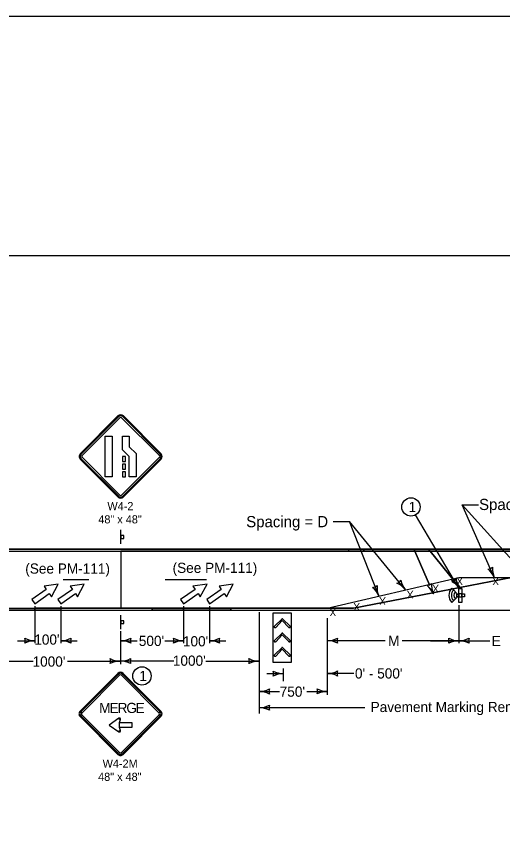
# Model space of a CAD drawing. Extents: x -2135039 to 114557, y -2139150 to -409929.
# Drawn here: x -2130293 to -2129338, y -2138203 to -2136566 of the extents above; entities that cross this region are included whole.
import ezdxf

# ---------------------------------------------------------------- set-up
doc = ezdxf.new("R2010")
doc.units = 0
for name, color, linetype in [('dsnDOTLogo', 7, 'Continuous'), ('dsnStdLabel', 7, 'Continuous'), ('dsnStdLineWork', 7, 'Continuous'), ('dsnStdNote', 7, 'Continuous'), ('dsnStdShading', 7, 'Continuous'), ('Level 1', 7, 'Continuous'), ('Level 2', 7, 'Continuous'), ('StdDimension', 7, 'Continuous')]:
    doc.layers.add(name, color=color, linetype=linetype)

msp = doc.modelspace()

# ---------------------------------------------------------------- linework, layer by layer
at = {"layer": 'dsnDOTLogo'}
msp.add_lwpolyline([(-2131438.9, -2139150.4), (-2128095, -2139150.4), (-2128095, -2136566.4), (-2131438.9, -2136566.4)], close=True, dxfattribs=at)
at = {"layer": 'dsnStdLabel'}
for p, q in [((-2130093.5, -2137351.4), (-2130167.7, -2137425.7)), ((-2130167.7, -2137425.7), (-2130093.5, -2137351.4)), ((-2130092.1, -2137352.7), (-2130166.4, -2137427)), ((-2130164.2, -2137429.2), (-2130089.9, -2137354.9)), ((-2130086.4, -2137354.9), (-2130086.4, -2137354.9)), ((-2130086.4, -2137354.9), (-2130012.1, -2137429.2)), ((-2130009.9, -2137427), (-2130084.2, -2137352.7)), ((-2130008.6, -2137425.7), (-2130082.9, -2137351.4)), ((-2130082.9, -2137351.4), (-2130008.6, -2137425.7)), ((-2130082.9, -2137351.4), (-2130082.9, -2137351.4)), ((-2130167.7, -2137436.3), (-2130093.5, -2137510.5)), ((-2130093.5, -2137510.5), (-2130167.7, -2137436.3)), ((-2130166.4, -2137434.9), (-2130092.1, -2137509.2)), ((-2130089.9, -2137507), (-2130164.2, -2137432.7)), ((-2130012.1, -2137432.7), (-2130086.4, -2137507)), ((-2130084.2, -2137509.2), (-2130009.9, -2137434.9)), ((-2130082.9, -2137510.5), (-2130008.6, -2137436.3)), ((-2130008.6, -2137436.3), (-2130082.9, -2137510.5)), ((-2130088, -2137602.9), (-2130088, -2137575.4)), ((-2129423.2, -2137717.6), (-2129423.2, -2137690.1)), ((-2129417.5, -2137690.3), (-2129417.5, -2137717.8)), ((-2130088, -2137770.4), (-2130088, -2137742.9)), ((-2129769.2, -2137750.6), (-2129755.1, -2137764.7)), ((-2129769.2, -2137778.7), (-2129755.1, -2137792.8)), ((-2129769.2, -2137806.9), (-2129755.1, -2137821)), ((-2130093.8, -2137857.5), (-2130168.1, -2137931.7)), ((-2130092.5, -2137858.8), (-2130090.3, -2137861)), ((-2130086.7, -2137861), (-2130084.5, -2137858.8)), ((-2130009, -2137931.7), (-2130083.2, -2137857.5)), ((-2130164.5, -2137935.3), (-2130166.7, -2137933)), ((-2130010.3, -2137933), (-2130012.5, -2137935.3)), ((-2130168.1, -2137942.3), (-2130093.8, -2138016.6)), ((-2130166.7, -2137941), (-2130164.5, -2137938.8)), ((-2130091.6, -2137945.6), (-2130090.5, -2137947.3)), ((-2130090.5, -2137947.3), (-2130088.6, -2137948)), ((-2130083.2, -2138016.6), (-2130009, -2137942.3)), ((-2130012.5, -2137938.8), (-2130010.3, -2137941)), ((-2130090.5, -2137970.5), (-2130091.6, -2137972.2)), ((-2130088.6, -2137969.8), (-2130090.5, -2137970.5)), ((-2130090.3, -2138013), (-2130092.5, -2138015.2)), ((-2130084.5, -2138015.2), (-2130086.7, -2138013))]:
    msp.add_line(p, q, dxfattribs=at)
for points in [[(-2130166.4, -2137427), (-2130092.1, -2137352.7)], [(-2130164.2, -2137429.2), (-2130089.9, -2137354.9)], [(-2130086.4, -2137354.9), (-2130012.1, -2137429.2)], [(-2130084.2, -2137352.7), (-2130009.9, -2137427)], [(-2130092.1, -2137509.2), (-2130166.4, -2137434.9)], [(-2130089.9, -2137507), (-2130164.2, -2137432.7)], [(-2130012.1, -2137432.7), (-2130086.4, -2137507)], [(-2130009.9, -2137434.9), (-2130084.2, -2137509.2)], [(-2129785.7, -2137764.7), (-2129785.7, -2137764.7), (-2129771.6, -2137750.6), (-2129771.6, -2137750.6)], [(-2129757.5, -2137767), (-2129757.5, -2137767), (-2129770.4, -2137753.4), (-2129783.3, -2137767)], [(-2129785.7, -2137792.8), (-2129785.7, -2137792.8), (-2129771.6, -2137778.7), (-2129771.6, -2137778.7)], [(-2129757.5, -2137795.1), (-2129757.5, -2137795), (-2129770.4, -2137781.5), (-2129783.3, -2137795.1)], [(-2129785.7, -2137821), (-2129785.7, -2137821), (-2129771.6, -2137806.9), (-2129771.6, -2137806.9)], [(-2129757.5, -2137823.3), (-2129757.5, -2137823.3), (-2129770.4, -2137809.7), (-2129783.3, -2137823.3)]]:
    msp.add_lwpolyline(points, dxfattribs=at)
for points in [[(-2130104.9, -2137391), (-2130104.9, -2137471), (-2130118.4, -2137471), (-2130118.4, -2137391)], [(-2130071.2, -2137412.1), (-2130057.9, -2137425.4), (-2130057.9, -2137471), (-2130071.4, -2137471), (-2130071.4, -2137431), (-2130084.7, -2137417.7), (-2130084.7, -2137391), (-2130071.2, -2137391)], [(-2130078.7, -2137431), (-2130084.7, -2137431), (-2130084.7, -2137441), (-2130078.7, -2137441)], [(-2130078.7, -2137446), (-2130084.7, -2137446), (-2130084.7, -2137456), (-2130078.7, -2137456)], [(-2130078.7, -2137461), (-2130084.7, -2137461), (-2130084.7, -2137471), (-2130078.7, -2137471)], [(-2130087.9, -2137586.5), (-2130087.9, -2137592.1), (-2130082.3, -2137592.1), (-2130082.3, -2137586.5)], [(-2129423.1, -2137717.8), (-2129423.1, -2137690.3), (-2129417.5, -2137690.3), (-2129417.5, -2137717.8)], [(-2129423.1, -2137701.1), (-2129423.1, -2137706.7), (-2129417.5, -2137706.7), (-2129417.5, -2137701.1)], [(-2129417.5, -2137706.7), (-2129417.5, -2137701.1), (-2129411.9, -2137701.1), (-2129411.9, -2137706.7)], [(-2130087.9, -2137754), (-2130087.9, -2137759.6), (-2130082.3, -2137759.6), (-2130082.3, -2137754)], [(-2129752.1, -2137835.1), (-2129752.1, -2137739.1), (-2129788.8, -2137739.1), (-2129788.8, -2137835.1)], [(-2130092.5, -2137858.8), (-2130166.7, -2137933), (-2130164.5, -2137935.3), (-2130090.3, -2137861), (-2130092.5, -2137858.8)], [(-2130010.3, -2137933), (-2130084.5, -2137858.8), (-2130086.7, -2137861), (-2130012.5, -2137935.3), (-2130010.3, -2137933)], [(-2130166.7, -2137941), (-2130092.5, -2138015.2), (-2130090.3, -2138013), (-2130164.5, -2137938.8), (-2130166.7, -2137941)], [(-2130110.9, -2137958.9), (-2130091.6, -2137972.2), (-2130090.5, -2137970.5), (-2130088.6, -2137969.8), (-2130090.6, -2137963.9), (-2130090.6, -2137953.9), (-2130088.6, -2137948), (-2130090.5, -2137947.3), (-2130091.6, -2137945.6), (-2130110.9, -2137958.9)], [(-2130084.5, -2138015.2), (-2130010.3, -2137941), (-2130012.5, -2137938.8), (-2130086.7, -2138013), (-2130084.5, -2138015.2)], [(-2130066.2, -2137953.9), (-2130066.2, -2137963.9), (-2130090.6, -2137963.9), (-2130090.6, -2137953.9), (-2130066.2, -2137953.9)]]:
    msp.add_lwpolyline(points, close=True, dxfattribs=at)
for centre, radius, start, end in [((-2130088.2, -2137356.7), 7.5, 45, 134.9997), ((-2130088.2, -2137356.7), 7.5, 45, 134.9997), ((-2130088.2, -2137356.7), 5.63, 45, 134.9997), ((-2130088.2, -2137356.7), 5.63, 45, 134.9997), ((-2130088.2, -2137356.7), 2.5, 45, 134.9997), ((-2130088.2, -2137356.7), 2.5, 45, 134.9997), ((-2130162.4, -2137431), 7.5, 134.9997, 225), ((-2130162.4, -2137431), 7.5, 134.9997, 225), ((-2130013.9, -2137431), 7.5, 315.0002, 44.9998), ((-2130013.9, -2137431), 7.5, 315.0002, 44.9998), ((-2130162.4, -2137431), 5.63, 134.9997, 225), ((-2130162.4, -2137431), 5.63, 134.9997, 225), ((-2130162.4, -2137431), 2.5, 134.9997, 225), ((-2130162.4, -2137431), 2.5, 134.9997, 225), ((-2130013.9, -2137431), 2.5, 315.0002, 44.9998), ((-2130013.9, -2137431), 2.5, 315.0002, 44.9998), ((-2130013.9, -2137431), 5.63, 315.0002, 44.9998), ((-2130013.9, -2137431), 5.63, 315.0002, 44.9998), ((-2130088.2, -2137505.2), 2.5, 225, 315.0002), ((-2130088.2, -2137505.2), 2.5, 225, 315.0002), ((-2130088.2, -2137505.2), 7.5, 225, 315.0002), ((-2130088.2, -2137505.2), 7.5, 225, 315.0002), ((-2130088.2, -2137505.2), 5.63, 225, 315.0002), ((-2130088.2, -2137505.2), 5.63, 225, 315.0002), ((-2129770.4, -2137751.8), 1.65, 44.1616, 134.6098), ((-2129784.5, -2137765.9), 1.65, 136.201, 317.3602), ((-2129756.3, -2137765.9), 1.65, 225.0975, 45.281), ((-2129770.4, -2137779.8), 1.65, 44.1616, 134.6098), ((-2129784.5, -2137793.9), 1.65, 136.201, 317.3602), ((-2129756.3, -2137793.9), 1.65, 225.0975, 45.281), ((-2129770.4, -2137808.1), 1.65, 44.1616, 134.6098), ((-2129784.5, -2137822.2), 1.65, 136.201, 317.3602), ((-2129756.3, -2137822.2), 1.65, 225.0975, 45.281), ((-2130088.5, -2137862.8), 7.5, 45, 134.9997), ((-2130088.5, -2137862.8), 5.62, 45, 134.9997), ((-2130088.5, -2137862.8), 2.5, 45, 134.9997), ((-2130162.8, -2137937), 7.5, 134.9997, 225), ((-2130162.8, -2137937), 5.62, 134.9997, 225), ((-2130014.3, -2137937), 5.62, 315.0002, 44.9998), ((-2130014.3, -2137937), 7.5, 315.0002, 44.9998), ((-2130162.8, -2137937), 2.5, 134.9997, 225), ((-2130090.5, -2137947.3), 2.03, 341.4187, 122.3124), ((-2130014.3, -2137937), 2.5, 315.0002, 44.9998), ((-2130090.5, -2137970.5), 2.03, 237.6875, 18.5819), ((-2130088.5, -2138011.3), 5.62, 225, 315.0002), ((-2130088.5, -2138011.3), 2.5, 225, 315.0002), ((-2130088.5, -2138011.3), 7.5, 225, 315.0002)]:
    msp.add_arc(centre, radius, start, end, dxfattribs=at)
at = {"layer": 'dsnStdLineWork'}
for p, q in [((-2129682, -2137728.9), (-2129423.2, -2137669.2)), ((-2129423.2, -2137669.2), (-2129275, -2137669.2)), ((-2130211, -2137682.1), (-2130238.7, -2137686.2)), ((-2130238.7, -2137686.2), (-2130234.4, -2137692.4)), ((-2130224.3, -2137706.7), (-2130211, -2137682.1)), ((-2130159.7, -2137682.1), (-2130187.4, -2137686.2)), ((-2130187.4, -2137686.2), (-2130183.1, -2137692.4)), ((-2130173, -2137706.7), (-2130159.7, -2137682.1)), ((-2129918.4, -2137682.1), (-2129946, -2137686.2)), ((-2129946, -2137686.2), (-2129941.7, -2137692.4)), ((-2129931.7, -2137706.7), (-2129918.4, -2137682.1)), ((-2129867.1, -2137682.1), (-2129894.7, -2137686.2)), ((-2129894.7, -2137686.2), (-2129890.4, -2137692.4)), ((-2129880.4, -2137706.7), (-2129867.1, -2137682.1)), ((-2130234.4, -2137692.4), (-2130263, -2137712.4)), ((-2130257.3, -2137720.6), (-2130228.6, -2137700.6)), ((-2130228.6, -2137700.6), (-2130224.3, -2137706.7)), ((-2130183.1, -2137692.4), (-2130211.7, -2137712.4)), ((-2130206, -2137720.6), (-2130177.3, -2137700.6)), ((-2130177.3, -2137700.6), (-2130173, -2137706.7)), ((-2129941.7, -2137692.4), (-2129970.4, -2137712.4)), ((-2129964.7, -2137720.6), (-2129936, -2137700.6)), ((-2129936, -2137700.6), (-2129931.7, -2137706.7)), ((-2129890.4, -2137692.4), (-2129919.1, -2137712.4)), ((-2129913.3, -2137720.6), (-2129884.7, -2137700.6)), ((-2129884.7, -2137700.6), (-2129880.4, -2137706.7)), ((-2130263, -2137712.4), (-2130257.3, -2137720.6)), ((-2130211.7, -2137712.4), (-2130206, -2137720.6)), ((-2129970.4, -2137712.4), (-2129964.7, -2137720.6)), ((-2129919.1, -2137712.4), (-2129913.3, -2137720.6)), ((-2131297.2, -2137728.9), (-2129682, -2137728.9))]:
    msp.add_line(p, q, dxfattribs=at)
for points in [[(-2131305.2, -2137616.9), (-2129275.6, -2137616.9)], [(-2130201, -2137672.9), (-2130151, -2137672.9)], [(-2130201, -2137672.9), (-2130151, -2137672.9)], [(-2130001, -2137672.9), (-2129951, -2137672.9)], [(-2129969.3, -2137672.9), (-2129919.3, -2137672.9)]]:
    msp.add_lwpolyline(points, dxfattribs=at)
at = {"layer": 'dsnStdNote'}
msp.add_circle((-2130046.4, -2137862.4), 18, dxfattribs=at)
at = {"layer": 'dsnStdShading'}
for p, q in [((-2131305.2, -2137616.9), (-2130088, -2137616.9)), ((-2131305.2, -2137616.9), (-2129509.7, -2137616.9)), ((-2131301.2, -2137612.9), (-2129174.6, -2137612.9)), ((-2129511.4, -2137612.9), (-2131301.2, -2137612.9)), ((-2130088, -2137616.9), (-2130088, -2137728.9)), ((-2129509.7, -2137616.9), (-2130088, -2137616.9)), ((-2130088, -2137616.9), (-2130088, -2137728.9)), ((-2129640.5, -2137612.9), (-2129612, -2137612.9)), ((-2129638.9, -2137616.9), (-2129640.5, -2137612.9)), ((-2129608.8, -2137616.9), (-2129638.9, -2137616.9)), ((-2129612, -2137612.9), (-2129608.8, -2137616.9)), ((-2129482.9, -2137612.9), (-2129511.4, -2137612.9)), ((-2129511.4, -2137612.9), (-2129509.7, -2137616.9)), ((-2129509.7, -2137616.9), (-2129511.4, -2137612.9)), ((-2129509.7, -2137616.9), (-2129479.7, -2137616.9)), ((-2129481, -2137683.4), (-2129509.7, -2137616.9)), ((-2129479.7, -2137616.9), (-2129509.7, -2137616.9)), ((-2129509.7, -2137616.9), (-2129481, -2137683.4)), ((-2129272.5, -2137612.9), (-2129482.9, -2137612.9)), ((-2129482.9, -2137612.9), (-2129479.7, -2137616.9)), ((-2129479.7, -2137616.9), (-2129482.9, -2137612.9)), ((-2129479.7, -2137616.9), (-2129270.9, -2137616.9)), ((-2129270.9, -2137616.9), (-2129479.7, -2137616.9)), ((-2129479.7, -2137616.9), (-2129432.4, -2137675.2)), ((-2129432.4, -2137675.2), (-2129479.7, -2137616.9)), ((-2129319.9, -2137669.2), (-2129421.4, -2137688.7)), ((-2129421.4, -2137688.7), (-2129319.9, -2137669.2)), ((-2129630.6, -2137728.9), (-2129474.4, -2137698.9)), ((-2129474.4, -2137698.9), (-2129630.6, -2137728.9)), ((-2129421.5, -2137688.7), (-2129474.3, -2137698.9)), ((-2129474.3, -2137698.9), (-2129421.5, -2137688.7)), ((-2129420.3, -2137690.2), (-2129420.7, -2137689.7)), ((-2131301.2, -2137732.9), (-2128969, -2137732.9)), ((-2130256.8, -2137732.9), (-2131301.2, -2137732.9)), ((-2130256.8, -2137728.9), (-2130256.8, -2137732.9)), ((-2130256.8, -2137732.9), (-2130256.8, -2137728.9)), ((-2130256.8, -2137728.9), (-2130205.9, -2137728.9)), ((-2130205.9, -2137732.9), (-2130256.8, -2137732.9)), ((-2129964.5, -2137728.9), (-2130205.9, -2137728.9)), ((-2130205.9, -2137728.9), (-2130205.9, -2137732.9)), ((-2130205.9, -2137728.9), (-2130205.9, -2137732.9)), ((-2130205.9, -2137732.9), (-2129964.5, -2137732.9)), ((-2130088, -2137728.9), (-2130026.1, -2137728.9)), ((-2130026.1, -2137728.9), (-2129871.5, -2137728.9)), ((-2129871.5, -2137728.9), (-2130026.1, -2137728.9)), ((-2130026.1, -2137728.9), (-2130026.1, -2137732.9)), ((-2130026.1, -2137732.9), (-2130026.1, -2137728.9)), ((-2130026.1, -2137728.9), (-2129871.5, -2137728.9)), ((-2129871.5, -2137732.9), (-2130026.1, -2137732.9)), ((-2130026.1, -2137732.9), (-2129871.5, -2137732.9)), ((-2129964.5, -2137732.9), (-2129964.5, -2137728.9)), ((-2129871.5, -2137732.9), (-2129871.5, -2137728.9)), ((-2129871.5, -2137728.9), (-2129871.5, -2137732.9)), ((-2129871.5, -2137728.9), (-2129630.6, -2137728.9)), ((-2129630.6, -2137728.9), (-2129871.5, -2137728.9)), ((-2129871.5, -2137728.9), (-2129871.5, -2137732.9)), ((-2129871.5, -2137732.9), (-2129040.8, -2137732.9))]:
    msp.add_line(p, q, dxfattribs=at)
for points in [[(-2129473.4, -2137701.1), (-2129473.4, -2137701.1), (-2129473.8, -2137700.2)], [(-2129473.8, -2137700.2), (-2129473.8, -2137700.2)], [(-2129421.5, -2137688.7), (-2129421.4, -2137688.7)], [(-2130088, -2137728.9), (-2130205.9, -2137728.9), (-2130256.8, -2137728.9)]]:
    msp.add_lwpolyline(points, dxfattribs=at)
for centre, radius, start, end in [((-2129442.5, -2137662.3), 16.4, 290.8549, 326.3216), ((-2129442.5, -2137662.3), 16.4, 308.0905, 326.3216), ((-2129387.1, -2137663.7), 42.5, 190.5158, 216.0585), ((-2129387.1, -2137663.7), 42.5, 190.5158, 216.0585), ((-2129487.2, -2137668.2), 16.4, 274.9287, 310.3954), ((-2129487.2, -2137668.2), 16.4, 274.9287, 291.9208), ((-2129512.6, -2137717.4), 42.5, 25.9041, 50.7345), ((-2129512.6, -2137717.5), 42.5, 23.928, 50.7345), ((-2129487.2, -2137668.2), 16.4, 291.9208, 310.3954), ((-2129434.2, -2137684.7), 42.5, 174.5895, 199.4578), ((-2129434.2, -2137684.7), 42.5, 174.5895, 199.4578), ((-2129442.5, -2137662.3), 16.4, 290.8549, 308.0905), ((-2129453.5, -2137716.7), 42.5, 41.1781, 66.6607), ((-2129453.5, -2137716.7), 42.5, 41.1781, 66.6607), ((-2129512.6, -2137717.4), 42.5, 23.928, 25.9041), ((-2129434.2, -2137684.7), 42.5, 199.4578, 202.6444), ((-2129434.2, -2137684.7), 42.5, 199.4578, 201.3966), ((-2129512.6, -2137717.4), 42.5, 22.662, 22.6796), ((-2129453.5, -2137716.7), 42.5, 39.4385, 41.1781), ((-2129387.1, -2137663.7), 42.5, 216.0585, 218.5706), ((-2129453.5, -2137716.7), 42.5, 38.5882, 38.6058), ((-2129387.1, -2137663.7), 42.5, 218.5875, 218.5882)]:
    msp.add_arc(centre, radius, start, end, dxfattribs=at)
at = {"layer": 'Level 1'}
msp.add_lwpolyline([(-2131334.4, -2137035.9), (-2128199.5, -2137035.9), (-2128199.5, -2139045.9), (-2131334.4, -2139045.9)], close=True, dxfattribs=at)
msp.add_circle((-2129517.4, -2137530.2), 18, dxfattribs=at)
at = {"layer": 'Level 2'}
for p, q in [((-2129437.3, -2137689.9), (-2129423.1, -2137704)), ((-2129423.1, -2137704), (-2129437.3, -2137718.2)), ((-2129417.5, -2137690.3), (-2129423.1, -2137690.3)), ((-2129417.5, -2137717.8), (-2129423.1, -2137717.8))]:
    msp.add_line(p, q, dxfattribs=at)
for radius, start, end in [(20.3, 135.88, 224.0313), (15.3, 136.1665, 223.7159), (10.3, 136.7294, 223.0963), (5.32, 138.7005, 221.2995)]:
    msp.add_arc((-2129422.6, -2137704.1), radius, start, end, dxfattribs=at)
at = {"layer": 'StdDimension'}
for p, q in [((-2129416.8, -2137525.8), (-2129384.8, -2137525.8)), ((-2129353.6, -2137668.8), (-2129416.8, -2137525.8)), ((-2129288.1, -2137668.8), (-2129416.8, -2137525.8)), ((-2129423.2, -2137690.1), (-2129508.2, -2137545.7)), ((-2129670.2, -2137558.7), (-2129638.2, -2137558.7)), ((-2129528.5, -2137692.8), (-2129638.2, -2137558.7)), ((-2129580.8, -2137705.1), (-2129638.2, -2137558.7)), ((-2130256.8, -2137725.5), (-2130256.8, -2137798.1)), ((-2130205.9, -2137725.5), (-2130205.9, -2137798.1)), ((-2129964.5, -2137725.5), (-2129964.5, -2137798.1)), ((-2129913.6, -2137725.5), (-2129913.6, -2137798.1)), ((-2129815.8, -2137737), (-2129815.8, -2137936.5)), ((-2129423.2, -2137723.3), (-2129423.2, -2137798.1)), ((-2129682, -2137748.9), (-2129682, -2137899.3)), ((-2130088.7, -2137774.7), (-2130088.7, -2137839.5)), ((-2130290.8, -2137793.1), (-2130256.8, -2137793.1)), ((-2130205.9, -2137793.1), (-2130173.9, -2137793.1)), ((-2130087.8, -2137793.1), (-2130055.7, -2137793.1)), ((-2130001.5, -2137793.1), (-2129964.5, -2137793.1)), ((-2129913.6, -2137793.1), (-2129881.6, -2137793.1)), ((-2129568, -2137793.1), (-2129682, -2137793.1)), ((-2129421.5, -2137793.2), (-2129534.9, -2137793.2)), ((-2129478.8, -2137793.2), (-2129362.5, -2137793.2)), ((-2130380.9, -2137833.3), (-2130260.2, -2137833.3)), ((-2130192.6, -2137833.3), (-2130088.7, -2137833.3)), ((-2129983.7, -2137833.3), (-2130088.7, -2137833.3)), ((-2129920.8, -2137833.3), (-2129815.8, -2137833.3)), ((-2129768.5, -2137847.6), (-2129768.5, -2137872.8)), ((-2129800.5, -2137857.9), (-2129768.5, -2137857.9)), ((-2129629.5, -2137857.7), (-2129682, -2137857.7)), ((-2129815.8, -2137893), (-2129775.8, -2137893)), ((-2129722, -2137893), (-2129682, -2137893)), ((-2129608.1, -2137924.9), (-2129815.8, -2137924.9))]:
    msp.add_line(p, q, dxfattribs=at)
for centre, radius, start, end in [((-2129367.3, -2137635.9), 16.4, 274.8945, 310.3612), ((-2129392.8, -2137685.2), 42.5, 22.6279, 50.7004), ((-2129314.4, -2137652.5), 42.5, 174.5554, 202.6279), ((-2129440.6, -2137659), 16.4, 281.5553, 317.0221), ((-2129386.1, -2137669.3), 42.5, 181.2162, 209.2887), ((-2129594.5, -2137672.2), 16.4, 274.9287, 310.3954), ((-2129620, -2137721.5), 42.5, 22.662, 50.7345), ((-2129541.6, -2137688.7), 42.5, 174.5895, 202.662), ((-2129550.7, -2137664.9), 16.4, 290.8549, 326.3216), ((-2129561.7, -2137719.3), 42.5, 38.5882, 66.6607), ((-2129495.3, -2137666.3), 42.5, 190.5158, 218.5882), ((-2129460.3, -2137710.8), 42.5, 29.2887, 57.3612), ((-2130292.4, -2137793.1), 16.4, 342.2667, 17.7334), ((-2130256.8, -2137750.6), 42.5, 241.9275, 270), ((-2130256.8, -2137835.6), 42.5, 90, 118.0725), ((-2130205.9, -2137750.6), 42.5, 270, 298.0725), ((-2130205.9, -2137835.6), 42.5, 61.9275, 90), ((-2130170.3, -2137793.1), 16.4, 162.2666, 197.7334), ((-2130088.4, -2137750.6), 42.5, 270, 298.0725), ((-2130088.4, -2137835.6), 42.5, 61.9275, 90), ((-2130052.8, -2137793.1), 16.4, 162.2666, 197.7334), ((-2130000.1, -2137793.1), 16.4, 342.2667, 17.7334), ((-2129964.5, -2137750.6), 42.5, 241.9275, 270), ((-2129964.5, -2137835.6), 42.5, 90, 118.0725), ((-2129913.6, -2137750.6), 42.5, 270, 298.0725), ((-2129913.6, -2137835.6), 42.5, 61.9275, 90), ((-2129878, -2137793.1), 16.4, 162.2666, 197.7334), ((-2129682, -2137750.6), 42.5, 270, 298.0725), ((-2129682, -2137835.6), 42.5, 61.9275, 90), ((-2129646.3, -2137793.1), 16.4, 162.2666, 197.7334), ((-2129458.8, -2137793.2), 16.4, 342.2667, 17.7334), ((-2129423.2, -2137750.7), 42.5, 241.9275, 270), ((-2129423.2, -2137835.7), 42.5, 90, 118.0725), ((-2129423.2, -2137750.7), 42.5, 270, 298.0725), ((-2129423.2, -2137835.7), 42.5, 61.9275, 90), ((-2129387.6, -2137793.2), 16.4, 162.2666, 197.7334), ((-2130124.3, -2137833.3), 16.4, 342.2667, 17.7334), ((-2130088.7, -2137790.8), 42.5, 241.9275, 270), ((-2130088.7, -2137875.8), 42.5, 90, 118.0725), ((-2130088.7, -2137790.8), 42.5, 270, 298.0725), ((-2130088.7, -2137875.8), 42.5, 61.9275, 90), ((-2130053, -2137833.3), 16.4, 162.2666, 197.7334), ((-2129851.5, -2137833.3), 16.4, 342.2667, 17.7334), ((-2129815.8, -2137790.8), 42.5, 241.9275, 270), ((-2129815.8, -2137875.8), 42.5, 90, 118.0725), ((-2129804.2, -2137857.9), 16.4, 342.2667, 17.7334), ((-2129768.5, -2137815.4), 42.5, 241.9275, 270), ((-2129768.5, -2137900.4), 42.5, 90, 118.0725), ((-2129682, -2137815.2), 42.5, 270, 298.0725), ((-2129682, -2137900.2), 42.5, 61.9275, 90), ((-2129646.3, -2137857.7), 16.4, 162.2666, 197.7334), ((-2129815.8, -2137850.5), 42.5, 270, 298.0725), ((-2129815.8, -2137935.5), 42.5, 61.9275, 90), ((-2129780.2, -2137893), 16.4, 162.2666, 197.7334), ((-2129717.6, -2137892.8), 16.4, 342.2667, 17.7334), ((-2129682, -2137850.3), 42.5, 241.9275, 270), ((-2129682, -2137935.3), 42.5, 90, 118.0725), ((-2129815.8, -2137882.4), 42.5, 270, 298.0725), ((-2129815.8, -2137967.4), 42.5, 61.9275, 90), ((-2129780.1, -2137924.9), 16.4, 162.2666, 197.7334)]:
    msp.add_arc(centre, radius, start, end, dxfattribs=at)

# ---------------------------------------------------------------- texts
at = {"layer": 'dsnStdLabel'}
for s, height, p in [('W4-2', 16, (-2130114.3, -2137536.6)), ('48" x 48"', 16, (-2130132.2, -2137562.6)), ('(See PM-111)', 20, (-2129986.1, -2137659.9)), ('(See PM-111)', 20, (-2130275.8, -2137661.3)), ('M', 20, (-2130130.4, -2137935.3)), ('E', 20, (-2130110.2, -2137935.3)), ('R', 20, (-2130094.2, -2137935.3)), ('G', 20, (-2130077, -2137935.3)), ('E', 20, (-2130058.8, -2137935.3)), ('W4-2M', 16, (-2130123.7, -2138042.7)), ('48" x 48"', 16, (-2130132.6, -2138068.7))]:
    msp.add_text(s, height=height, dxfattribs=at).set_placement(p)
for p in [(-2129414.8, -2137668.6), (-2129344.1, -2137668.6), (-2129462.2, -2137683), (-2129512.3, -2137694.8), (-2129617.4, -2137718.9), (-2129566.6, -2137707.5), (-2129664.2, -2137729.5)]:
    msp.add_text('X', height=15, rotation=180, dxfattribs=at).set_placement(p)
at = {"layer": 'dsnStdNote'}
msp.add_text('1', height=20, dxfattribs=at).set_placement((-2130051.6, -2137872.4))
at = {"layer": 'Level 1'}
msp.add_text('1', height=20, dxfattribs=at).set_placement((-2129522.1, -2137540.2))
at = {"layer": 'StdDimension'}
for s, height, p in [('Spacing = D', 22, (-2129383.4, -2137536.3)), ('Spacing = D', 22, (-2129841.3, -2137570.1)), ("100'", 20, (-2130258.1, -2137800.9)), ("500'", 20, (-2130052.5, -2137803.5)), ("100'", 20, (-2129965.8, -2137804.3)), ('M', 20, (-2129562.3, -2137803.4)), ('E', 20, (-2129358.6, -2137803.7)), ("1000'", 20, (-2130261.5, -2137844.1)), ("1000'", 20, (-2129985.6, -2137842.4)), ("0' - 500'", 20, (-2129627.5, -2137867.5)), ("750'", 20, (-2129775.5, -2137903.3)), ('Pavement Marking Removal Limits', 20, (-2129596.7, -2137933.4))]:
    msp.add_text(s, height=height, dxfattribs=at).set_placement(p)

doc.saveas('drawing.dxf')
